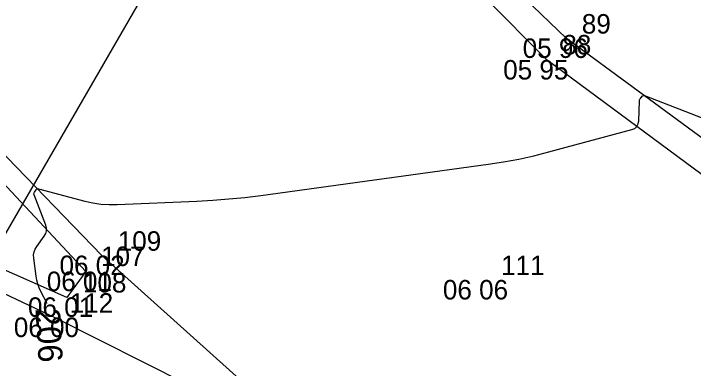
# Model space of a CAD drawing. Extents: x -711234 to -710007, y -1026313 to -1025448.
# Drawn here: x -711048.26 to -711038.49, y -1025884.37 to -1025879.27 of the extents above; entities that cross this region are included whole.
import ezdxf

# ---------------------------------------------------------------- set-up
doc = ezdxf.new("R2010")
doc.units = 0
for name, color, linetype in [('Ex_Contour Labels', 7, 'Continuous'), ('Ex_Major Contours', 7, 'Continuous'), ('Z_body', 7, 'Continuous'), ('Z_body_cisla', 7, 'Continuous'), ('Z_body_vysky_redukovane', 7, 'Continuous'), ('Z_komunikace', 7, 'Continuous'), ('Z_propustek', 7, 'Continuous'), ('Z_vdz25_plna', 7, 'Continuous')]:
    doc.layers.add(name, color=color, linetype=linetype)

# ---------------------------------------------------------------- blocks, each defined once
blk = doc.blocks.new('POINT_DISPLAY')
blk.add_line((0, 0), (0, 0))

msp = doc.modelspace()

# ---------------------------------------------------------------- linework, layer by layer
at = {"layer": 'Ex_Major Contours'}
msp.add_lwpolyline([(-711047.7743, -1025883.4395), (-711047.8649, -1025883.2652), (-711047.8896, -1025883.2122), (-711047.9093, -1025883.1577), (-711047.924, -1025883.1017), (-711047.9339, -1025883.0441), (-711047.9665, -1025882.7849), (-711047.9682, -1025882.7405), (-711047.9616, -1025882.6982), (-711047.9469, -1025882.6581), (-711047.924, -1025882.62), (-711047.816, -1025882.472), (-711047.7944, -1025882.4343), (-711047.7837, -1025882.3951), (-711047.7839, -1025882.3545), (-711047.7949, -1025882.3125), (-711047.9623, -1025881.8767), (-711047.9649, -1025881.8669), (-711047.9649, -1025881.8573), (-711047.9625, -1025881.8481), (-711047.9575, -1025881.8392), (-711047.9325, -1025881.8042), (-711047.9257, -1025881.7969), (-711047.9179, -1025881.7924), (-711047.9091, -1025881.7908), (-711047.8992, -1025881.7921), (-711047.2321, -1025881.967), (-711047.117, -1025881.9927), (-711047.001, -1025882.0095), (-711046.884, -1025882.0176), (-711046.766, -1025882.0169), (-711045.6218, -1025881.9671), (-711045.3918, -1025881.9545), (-711045.1624, -1025881.9365), (-711044.9334, -1025881.9132), (-711044.7049, -1025881.8846), (-711041.4354, -1025881.4368), (-711041.2157, -1025881.4031), (-711040.9973, -1025881.3626), (-711040.7804, -1025881.3151), (-711040.5648, -1025881.2607), (-711039.3733, -1025880.9401), (-711039.3304, -1025880.9223), (-711039.2992, -1025880.8951), (-711039.2799, -1025880.8587), (-711039.2723, -1025880.8129), (-711039.2627, -1025880.5317), (-711039.2616, -1025880.5211), (-711039.2588, -1025880.5112), (-711039.2545, -1025880.5018), (-711039.2485, -1025880.493), (-711039.2215, -1025880.459), (-711039.2143, -1025880.4521), (-711039.2063, -1025880.4482), (-711039.1975, -1025880.4475), (-711039.1878, -1025880.4499), (-711036.5897, -1025881.4615)], dxfattribs=at)
at = {"layer": 'Z_komunikace'}
for p, q in [((-711040.31, -1025879.63), (-711045.08, -1025875.01)), ((-711034.8, -1025883.69), (-711040.31, -1025879.63)), ((-711049.93, -1025880.07), (-711047.22, -1025882.98)), ((-711047.49, -1025883.35), (-711052.64, -1025881.08)), ((-711047.22, -1025882.98), (-711047.49, -1025883.35))]:
    msp.add_line(p, q, dxfattribs=at)
at = {"layer": 'Z_propustek'}
msp.add_line((-711053.28, -1025890.92), (-711042.93, -1025873.02), dxfattribs=at)
at = {"layer": 'Z_vdz25_plna'}
for p, q in [((-711040.59, -1025879.94), (-711045.31, -1025875.18)), ((-711049.78, -1025879.86), (-711046.99, -1025882.75)), ((-711035.07, -1025884.03), (-711040.59, -1025879.94)), ((-711047.67, -1025883.64), (-711052.75, -1025881.24)), ((-711046.99, -1025882.75), (-711043.86, -1025885.55)), ((-711043.86, -1025885.55), (-711047.67, -1025883.64))]:
    msp.add_line(p, q, dxfattribs=at)

# ---------------------------------------------------------------- block references
at = {"layer": 'Z_body'}
for p in [(-711040.31, -1025879.63), (-711040.59, -1025879.94), (-711046.99, -1025882.75), (-711047.22, -1025882.98), (-711041.48, -1025883.1), (-711047.49, -1025883.35), (-711047.67, -1025883.64)]:
    msp.add_blockref('POINT_DISPLAY', p, dxfattribs=at)

# ---------------------------------------------------------------- texts
at = {"layer": 'Ex_Contour Labels'}
msp.add_text('206', height=0.35, rotation=273.45397, dxfattribs=at).set_placement((-711047.9434, -1025883.5145))
at = {"layer": 'Z_body_cisla'}
for s, p in [('89', (-711040.09, -1025879.56)), ('88', (-711040.37, -1025879.86)), ('109', (-711046.76, -1025882.68)), ('107', (-711047, -1025882.9)), ('111', (-711041.25, -1025883.03)), ('108', (-711047.26, -1025883.28)), ('112', (-711047.45, -1025883.57))]:
    msp.add_text(s, height=0.28, dxfattribs=at).set_placement(p)
at = {"layer": 'Z_body_vysky_redukovane'}
for s, p in [('05 96', (-711040.94, -1025879.91)), ('05 95', (-711041.22, -1025880.22)), ('06 02', (-711047.5967, -1025883.03)), ('06 01', (-711047.78, -1025883.26)), ('06 06', (-711042.0867, -1025883.38)), ('06 01', (-711048.05, -1025883.63)), ('06 00', (-711048.2533, -1025883.92))]:
    msp.add_text(s, height=0.28, dxfattribs=at).set_placement(p)

doc.saveas('drawing.dxf')
